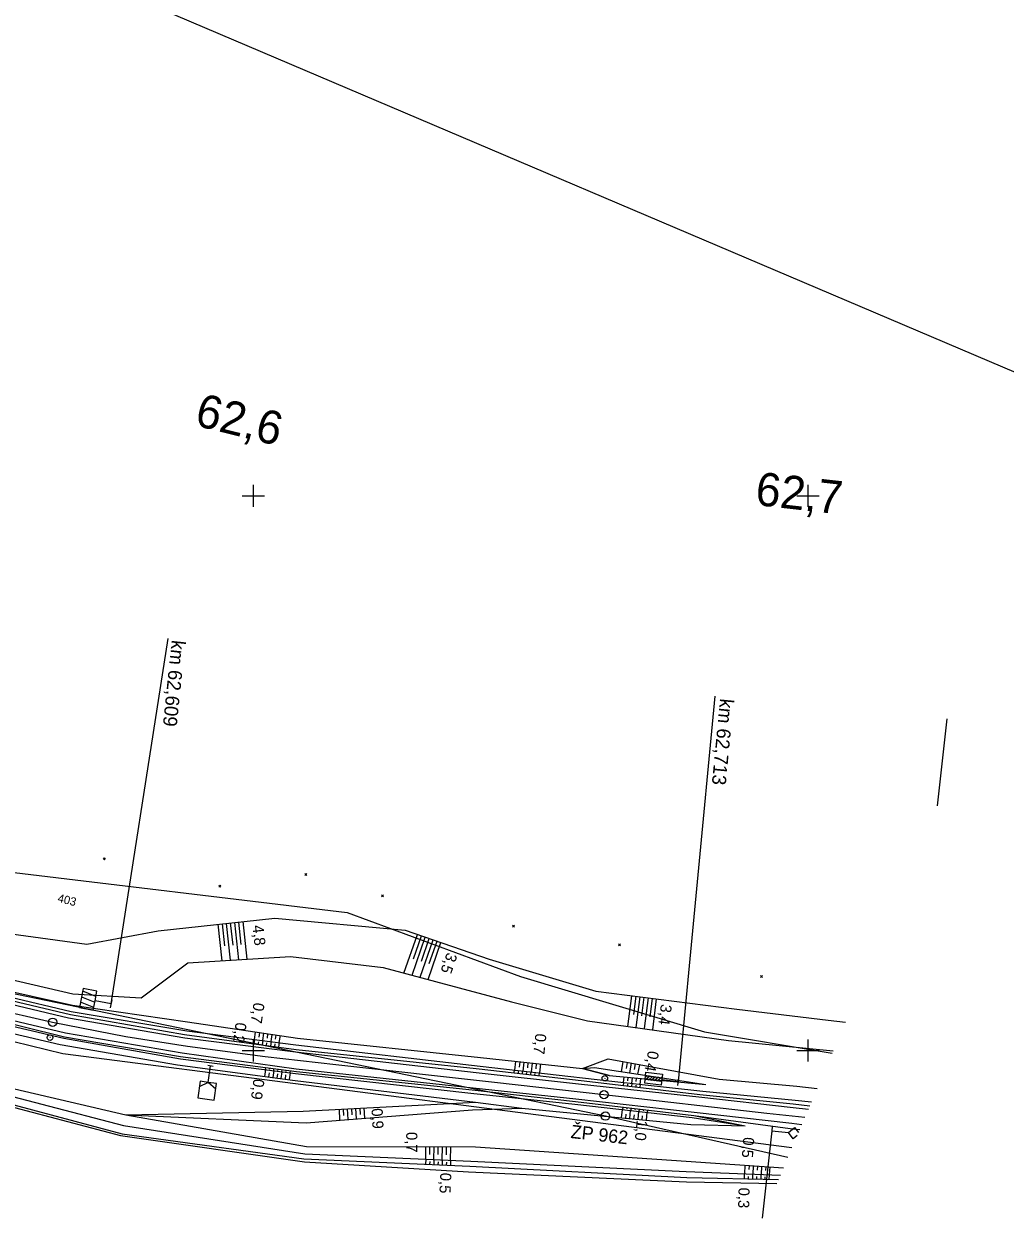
# Model space of a CAD drawing. Extents: x -805636 to -804553, y -1165340 to -1164656.
# Drawn here: x -804941.3 to -804764.5, y -1165130.2 to -1164914.9 of the extents above; entities that cross this region are included whole.
import ezdxf

# ---------------------------------------------------------------- set-up
doc = ezdxf.new("R2010")
doc.units = 0
for name, color, linetype in [('0381KM061-064P - Vrstva 1', 7, 'Continuous'), ('0381KM061-064P - Vrstva 4', 7, 'Continuous'), ('0381KM061-064P - Vrstva 48', 7, 'Continuous'), ('0381KM061-064P - Vrstva 49', 7, 'Continuous'), ('0381KM061-064P - Vrstva 51', 7, 'Continuous'), ('0381KM061-064P - Vrstva 57', 7, 'Continuous'), ('0381KM061-064P - Vrstva 7', 7, 'Continuous'), ('0381KM061-064P - Vrstva 8', 7, 'Continuous'), ('formát', 7, 'Continuous'), ('hran DP - hran DP', 7, 'Continuous'), ('krizky_1000 - Vrstva 1', 7, 'Continuous'), ('vyt_sit - polygon', 7, 'Continuous'), ('vyt_sit - stávající', 7, 'Continuous')]:
    doc.layers.add(name, color=color, linetype=linetype)

msp = doc.modelspace()

# ---------------------------------------------------------------- linework, layer by layer
at = {"layer": '0381KM061-064P - Vrstva 1'}
for points in [[(-805053.13, -1165050.53), (-805043.64, -1165055.76), (-805030.64, -1165062.45), (-805014.61, -1165069.88), (-804997.39, -1165076.92), (-804978.26, -1165083.66), (-804962.13, -1165088.54), (-804947.73, -1165092.28), (-804936.17, -1165094.91), (-804922.95, -1165097.46), (-804911.85, -1165099.22)], [(-804911.85, -1165099.22), (-804897.85, -1165101.07), (-804885.13, -1165102.52)], [(-804885.13, -1165102.52), (-804856.51, -1165105.73), (-804836.78, -1165107.96), (-804807.43, -1165111.28), (-804800.55, -1165112.05)]]:
    msp.add_lwpolyline(points, dxfattribs=at)
at = {"layer": '0381KM061-064P - Vrstva 4'}
for points in [[(-805080.47, -1165032.5), (-805059.19, -1165045.48), (-805045.86, -1165053.03), (-805029.76, -1165061.31), (-805010.76, -1165070.1), (-804990.66, -1165078.03), (-804974.85, -1165083.28), (-804955.57, -1165088.82), (-804933.31, -1165094.09), (-804912.36, -1165097.73), (-804892.37, -1165100.24)], [(-805080.11, -1165031.8), (-805059.18, -1165044.72), (-805045.31, -1165052.51), (-805029.54, -1165060.96), (-805010.72, -1165069.47), (-804990.45, -1165077.48), (-804974.57, -1165082.73), (-804955.28, -1165088.2), (-804932.96, -1165093.51), (-804912.39, -1165097.1), (-804892.28, -1165099.85)], [(-805082.03, -1165034.98), (-805060.37, -1165047.85), (-805047.54, -1165055.28), (-805031.06, -1165063.92), (-805012.89, -1165072.24), (-804991.69, -1165080.62), (-804976.05, -1165085.82), (-804956.42, -1165091.49), (-804933.87, -1165096.82), (-804912.82, -1165100.43), (-804892.24, -1165103.28)], [(-805082.08, -1165035.58), (-805060.58, -1165048.58), (-805047.98, -1165055.77), (-805031.23, -1165064.28), (-805013.07, -1165072.73), (-804991.62, -1165081.24), (-804976.47, -1165086.37), (-804956.64, -1165091.96), (-804934.05, -1165097.54), (-804913.13, -1165101.06), (-804892.22, -1165103.81)], [(-804892.37, -1165100.24), (-804859.84, -1165103.98), (-804840.8, -1165106.06), (-804819.65, -1165108.38), (-804802.7, -1165110.3), (-804799.92, -1165110.56)], [(-804892.28, -1165099.85), (-804859.81, -1165103.25), (-804840.34, -1165105.46), (-804819.52, -1165107.92), (-804802.69, -1165109.64), (-804799.68, -1165110)], [(-804892.24, -1165103.28), (-804860.33, -1165106.74), (-804841.86, -1165108.69), (-804820.53, -1165111.13), (-804802.92, -1165113.13), (-804801.1, -1165113.34)], [(-804892.22, -1165103.81), (-804860.51, -1165107.09), (-804841.9, -1165109.22), (-804820.58, -1165111.74), (-804803.21, -1165114.08), (-804801.49, -1165114.25)]]:
    msp.add_lwpolyline(points, dxfattribs=at)
at = {"layer": '0381KM061-064P - Vrstva 48'}
for p, q in [((-804905.61, -1165083.83), (-804906.31, -1165077.25)), ((-804905.14, -1165081.14), (-804905.57, -1165077.17)), ((-804904.11, -1165083.73), (-804904.83, -1165077.09)), ((-804903.65, -1165081.01), (-804904.08, -1165077.01)), ((-804902.62, -1165083.64), (-804903.34, -1165076.93)), ((-804902.16, -1165080.89), (-804902.59, -1165076.85)), ((-804901.12, -1165083.54), (-804901.85, -1165076.77)), ((-804872.83, -1165086.04), (-804870.41, -1165079.07)), ((-804871.37, -1165086.42), (-804868.99, -1165079.56)), ((-804871.14, -1165083.47), (-804869.7, -1165079.32)), ((-804869.92, -1165086.81), (-804867.58, -1165080.06)), ((-804869.7, -1165083.89), (-804868.29, -1165079.81)), ((-804868.47, -1165087.2), (-804866.16, -1165080.55)), ((-804868.26, -1165084.32), (-804866.87, -1165080.3)), ((-804832.45, -1165095.65), (-804831.74, -1165090.13)), ((-804831.42, -1165093.54), (-804831, -1165090.23)), ((-804830.97, -1165095.86), (-804830.25, -1165090.32)), ((-804829.94, -1165093.74), (-804829.51, -1165090.42)), ((-804829.48, -1165096.06), (-804828.77, -1165090.52)), ((-804828.45, -1165093.95), (-804828.02, -1165090.61)), ((-804827.99, -1165096.27), (-804827.28, -1165090.71)), ((-804899.77, -1165098.02), (-804899.57, -1165096.67)), ((-804898.95, -1165097.58), (-804898.83, -1165096.78)), ((-804898.29, -1165098.2), (-804898.09, -1165096.89)), ((-804897.46, -1165097.78), (-804897.35, -1165097)), ((-804896.8, -1165098.39), (-804896.61, -1165097.11)), ((-804895.98, -1165097.98), (-804895.87, -1165097.22)), ((-804895.31, -1165098.58), (-804895.12, -1165097.33)), ((-804899.78, -1165098.02), (-804899.89, -1165098.81)), ((-804899.08, -1165098.43), (-804899.15, -1165098.91)), ((-804898.29, -1165098.2), (-804898.4, -1165099.01)), ((-804897.59, -1165098.62), (-804897.66, -1165099.12)), ((-804896.8, -1165098.39), (-804896.92, -1165099.22)), ((-804896.11, -1165098.82), (-804896.17, -1165099.32)), ((-804895.32, -1165098.58), (-804895.43, -1165099.42)), ((-804897.81, -1165103.45), (-804897.97, -1165104.67)), ((-804897.8, -1165103.45), (-804897.75, -1165103.08)), ((-804897.04, -1165103.4), (-804897.01, -1165103.18)), ((-804896.32, -1165103.64), (-804896.49, -1165104.86)), ((-804896.31, -1165103.64), (-804896.27, -1165103.28)), ((-804895.55, -1165103.59), (-804895.52, -1165103.38)), ((-804894.83, -1165103.83), (-804895, -1165105.06)), ((-804894.83, -1165103.83), (-804894.78, -1165103.48)), ((-804894.06, -1165103.78), (-804894.04, -1165103.57)), ((-804893.34, -1165104.02), (-804893.29, -1165103.67)), ((-804852.96, -1165103.52), (-804853.02, -1165104.02)), ((-804852.82, -1165103.53), (-804852.66, -1165101.96)), ((-804852.24, -1165103.8), (-804852.27, -1165104.11)), ((-804852.01, -1165102.99), (-804851.91, -1165102.04)), ((-804851.47, -1165103.69), (-804851.53, -1165104.19)), ((-804851.33, -1165103.71), (-804851.17, -1165102.11)), ((-804850.52, -1165103.15), (-804850.42, -1165102.19)), ((-804849.98, -1165103.86), (-804850.04, -1165104.36)), ((-804849.84, -1165103.88), (-804849.67, -1165102.27)), ((-804849.03, -1165103.32), (-804848.93, -1165102.35)), ((-804848.35, -1165104.05), (-804848.18, -1165102.43)), ((-804833.61, -1165103.81), (-804833.29, -1165102.02)), ((-804832.74, -1165103.22), (-804832.55, -1165102.15)), ((-804832.13, -1165104.04), (-804831.81, -1165102.29)), ((-804831.26, -1165103.46), (-804831.07, -1165102.42)), ((-804830.65, -1165104.27), (-804830.33, -1165102.56)), ((-804897.13, -1165104.03), (-804897.23, -1165104.77)), ((-804895.64, -1165104.23), (-804895.74, -1165104.97)), ((-804894.16, -1165104.42), (-804894.26, -1165105.16)), ((-804893.35, -1165104.02), (-804893.51, -1165105.26)), ((-804850.75, -1165103.98), (-804850.78, -1165104.28)), ((-804849.26, -1165104.15), (-804849.29, -1165104.44)), ((-804848.49, -1165104.04), (-804848.55, -1165104.53)), ((-804833.23, -1165105.8), (-804833.29, -1165106.29)), ((-804833.24, -1165105.79), (-804833.15, -1165104.77)), ((-804832.46, -1165105.46), (-804832.4, -1165104.84)), ((-804831.74, -1165105.96), (-804831.8, -1165106.47)), ((-804831.75, -1165105.96), (-804831.66, -1165104.91)), ((-804830.97, -1165105.61), (-804830.91, -1165104.98)), ((-804830.26, -1165106.12), (-804830.16, -1165105.05)), ((-804832.51, -1165106.08), (-804832.54, -1165106.38)), ((-804831.02, -1165106.25), (-804831.05, -1165106.55)), ((-804830.25, -1165106.12), (-804830.31, -1165106.64)), ((-804833.4, -1165110.23), (-804833.45, -1165110.65)), ((-804832.66, -1165110.31), (-804832.68, -1165110.53)), ((-804884.38, -1165112.57), (-804884.48, -1165110.6)), ((-804883.67, -1165111.73), (-804883.73, -1165110.56)), ((-804882.88, -1165112.45), (-804882.99, -1165110.52)), ((-804882.18, -1165111.63), (-804882.24, -1165110.48)), ((-804881.39, -1165112.33), (-804881.49, -1165110.44)), ((-804880.68, -1165111.53), (-804880.74, -1165110.4)), ((-804879.89, -1165112.22), (-804879.99, -1165110.36)), ((-804833.61, -1165112.12), (-804833.46, -1165110.65)), ((-804832.86, -1165112.2), (-804832.79, -1165111.47)), ((-804832.11, -1165112.27), (-804831.97, -1165110.82)), ((-804831.91, -1165110.4), (-804831.96, -1165110.82)), ((-804831.37, -1165112.34), (-804831.3, -1165111.62)), ((-804831.17, -1165110.49), (-804831.19, -1165110.7)), ((-804830.62, -1165112.41), (-804830.48, -1165111)), ((-804830.42, -1165110.58), (-804830.47, -1165111)), ((-804829.87, -1165112.48), (-804829.81, -1165111.78)), ((-804829.68, -1165110.67), (-804829.7, -1165110.87)), ((-804829.13, -1165112.56), (-804828.99, -1165111.17)), ((-804828.93, -1165110.75), (-804828.98, -1165111.17)), ((-804868.92, -1165119.6), (-804868.91, -1165117.37)), ((-804868.17, -1165118.73), (-804868.16, -1165117.37)), ((-804867.42, -1165119.67), (-804867.41, -1165117.37)), ((-804866.67, -1165118.77), (-804866.66, -1165117.38)), ((-804865.92, -1165119.74), (-804865.91, -1165117.38)), ((-804865.17, -1165118.81), (-804865.16, -1165117.38)), ((-804864.42, -1165119.8), (-804864.41, -1165117.38)), ((-804868.92, -1165119.6), (-804868.96, -1165120.51)), ((-804868.18, -1165120), (-804868.21, -1165120.54)), ((-804867.42, -1165119.67), (-804867.46, -1165120.58)), ((-804866.68, -1165120.06), (-804866.71, -1165120.61)), ((-804865.92, -1165119.74), (-804865.96, -1165120.65)), ((-804865.19, -1165120.13), (-804865.21, -1165120.68)), ((-804864.42, -1165119.8), (-804864.46, -1165120.71)), ((-804811.36, -1165120.67), (-804811.46, -1165122.21)), ((-804810.61, -1165120.72), (-804810.66, -1165121.48)), ((-804809.86, -1165120.78), (-804809.96, -1165122.27)), ((-804809.11, -1165120.83), (-804809.16, -1165121.56)), ((-804808.36, -1165120.88), (-804808.46, -1165122.33)), ((-804807.62, -1165120.93), (-804807.67, -1165121.65)), ((-804806.87, -1165120.98), (-804806.97, -1165122.39)), ((-804811.47, -1165123.14), (-804811.45, -1165122.21)), ((-804810.72, -1165123.15), (-804810.71, -1165122.7)), ((-804809.97, -1165123.17), (-804809.95, -1165122.27)), ((-804809.22, -1165123.19), (-804809.21, -1165122.74)), ((-804808.47, -1165123.2), (-804808.45, -1165122.33)), ((-804807.72, -1165123.22), (-804807.71, -1165122.79)), ((-804806.97, -1165123.24), (-804806.95, -1165122.39))]:
    msp.add_line(p, q, dxfattribs=at)
at = {"layer": '0381KM061-064P - Vrstva 49'}
for p, q in [((-804926.67, -1165065.65), (-804927.02, -1165065.3)), ((-804926.67, -1165065.3), (-804927.02, -1165065.65)), ((-804890.35, -1165068.45), (-804890.7, -1165068.09)), ((-804890.35, -1165068.09), (-804890.7, -1165068.45)), ((-804905.87, -1165070.56), (-804906.22, -1165070.21)), ((-804905.87, -1165070.21), (-804906.22, -1165070.56)), ((-804876.55, -1165072.32), (-804876.9, -1165071.96)), ((-804876.55, -1165071.96), (-804876.9, -1165072.32)), ((-804852.89, -1165077.76), (-804853.25, -1165077.4)), ((-804852.89, -1165077.4), (-804853.25, -1165077.76)), ((-804833.78, -1165081.15), (-804834.13, -1165080.8)), ((-804833.78, -1165080.8), (-804834.13, -1165081.15)), ((-804808.18, -1165086.83), (-804808.54, -1165086.48)), ((-804808.18, -1165086.48), (-804808.54, -1165086.83))]:
    msp.add_line(p, q, dxfattribs=at)
for points in [[(-805084.74, -1165039.06), (-805061.55, -1165052.74), (-805034.17, -1165068.7), (-805016.31, -1165078.58), (-804984.31, -1165094.26), (-804952.92, -1165105.84), (-804923.4, -1165113.55), (-804890.69, -1165118.62), (-804860.79, -1165119.97), (-804821.99, -1165121.8), (-804804.98, -1165122.47)], [(-805085.43, -1165039.91), (-805061.8, -1165053.37), (-805034.45, -1165069.27), (-805016.82, -1165079.3), (-804984.87, -1165094.97), (-804952.63, -1165107.29), (-804923.66, -1165115.02), (-804890.91, -1165119.51), (-804860.93, -1165120.87), (-804821.85, -1165122.9), (-804805.33, -1165123.27)], [(-805060.73, -1165049.17), (-805031.5, -1165064.84), (-805013.36, -1165073.14), (-804991.7, -1165081.91), (-804976.67, -1165086.76), (-804957.06, -1165092.46), (-804934.14, -1165097.81), (-804913.12, -1165101.52), (-804892.37, -1165104.14)], [(-805060.73, -1165049.17), (-805047.98, -1165055.77), (-805031.23, -1165064.28), (-805013.07, -1165072.73), (-804991.62, -1165081.24), (-804976.47, -1165086.37), (-804956.64, -1165091.96), (-804934.05, -1165097.54), (-804913.13, -1165101.06), (-804892.22, -1165103.81), (-804860.51, -1165107.09), (-804841.9, -1165109.22), (-804820.58, -1165111.74), (-804811.31, -1165113.56)], [(-805014.74, -1165060.42), (-805013.72, -1165061.35), (-805008.65, -1165063.79), (-805007.41, -1165061.32), (-805005.07, -1165061.94), (-804999.18, -1165065.52), (-804973.34, -1165074.67), (-804953.36, -1165077.67), (-804930.03, -1165080.86)], [(-805033.41, -1165066.35), (-805014.98, -1165076.25), (-804982.53, -1165092.31), (-804953.12, -1165104.6), (-804922.96, -1165111.59), (-804890.43, -1165117.32), (-804859.92, -1165117.39), (-804821.94, -1165119.94), (-804804.42, -1165121.15)], [(-805032.39, -1165065.25), (-805013.72, -1165073.73), (-804991.69, -1165082.79), (-804976.92, -1165087.4), (-804957.71, -1165093.59), (-804934.8, -1165098.93), (-804913.68, -1165102.56), (-804892.44, -1165105.41)], [(-805010.72, -1165069.47), (-804990.45, -1165077.48), (-804974.57, -1165082.73), (-804955.28, -1165088.2), (-804932.96, -1165093.51), (-804912.39, -1165097.1), (-804892.28, -1165099.85), (-804859.81, -1165103.25), (-804840.34, -1165105.46), (-804819.52, -1165107.92), (-804802.69, -1165109.64), (-804799.68, -1165110)], [(-804995.17, -1165073.22), (-804973.67, -1165080.7), (-804954.98, -1165086.86), (-804932.57, -1165091.85), (-804911.87, -1165094.85)], [(-804994.86, -1165072.51), (-804973.16, -1165079.86), (-804954.29, -1165084.75), (-804932.5, -1165089.79), (-804920.22, -1165090.5), (-804911.77, -1165084.22), (-804893.29, -1165083.05), (-804876.57, -1165085.04), (-804853.44, -1165091.21), (-804839.72, -1165094.63), (-804814.35, -1165098.18)], [(-804930.03, -1165080.86), (-804917.17, -1165078.41), (-804896.14, -1165076.16), (-804872.64, -1165078.3), (-804857.5, -1165083.55), (-804838.27, -1165089.29), (-804812.85, -1165092.56), (-804796.39, -1165094.52), (-804793.24, -1165094.87)], [(-804955.12, -1165087.69), (-804932.8, -1165092.95), (-804911.98, -1165096.48), (-804892.31, -1165098.96)], [(-804911.87, -1165094.85), (-804892.03, -1165097.79)], [(-804892.31, -1165098.96), (-804859.08, -1165102.8), (-804835.93, -1165105.5), (-804818.93, -1165107.36), (-804802.32, -1165108.93), (-804799.37, -1165109.27)], [(-804892.03, -1165097.79), (-804859.05, -1165101.29), (-804840.64, -1165103.22)], [(-804814.35, -1165098.18), (-804795.44, -1165100.05)], [(-804840.64, -1165103.22), (-804836.05, -1165101.51), (-804816.03, -1165105.18), (-804802.02, -1165106.41), (-804798.34, -1165106.84)], [(-804840.64, -1165103.22), (-804838.47, -1165103.07), (-804818.4, -1165106.14)], [(-804840.64, -1165103.22), (-804835.82, -1165104.53), (-804840.64, -1165103.22), (-804835.82, -1165104.53), (-804818.4, -1165106.14)], [(-804892.44, -1165105.41), (-804859.96, -1165109.29), (-804851.61, -1165110.39), (-804821.13, -1165113.33), (-804811.31, -1165113.56)], [(-804892.37, -1165104.14), (-804860.79, -1165107.69), (-804842.05, -1165109.66), (-804820.85, -1165112.11), (-804811.31, -1165113.56)], [(-804922.96, -1165111.59), (-804890.98, -1165110.95), (-804859.96, -1165109.29)], [(-804922.96, -1165111.59), (-804890.49, -1165113.04), (-804860.47, -1165110.71), (-804851.61, -1165110.39)]]:
    msp.add_lwpolyline(points, dxfattribs=at)
at = {"layer": '0381KM061-064P - Vrstva 51'}
msp.add_lwpolyline([(-805085.93, -1165040.55), (-805062.08, -1165054.12), (-805034.69, -1165069.73), (-805017.21, -1165079.65), (-804985.71, -1165095.39), (-804952.66, -1165107.75), (-804923.93, -1165115.31), (-804890.75, -1165120.1), (-804861.18, -1165121.85), (-804821.92, -1165123.67), (-804805.64, -1165124)], dxfattribs=at)
at = {"layer": '0381KM061-064P - Vrstva 7'}
for p, q in [((-804925.59, -1165091.6), (-804915.32, -1165025.75)), ((-804930.94, -1165090.31), (-804928.58, -1165091.28)), ((-804928.39, -1165090.29), (-804930.75, -1165089.33)), ((-804925.73, -1165092.34), (-804925.45, -1165090.86)), ((-804928.77, -1165092.26), (-804931.13, -1165091.29)), ((-804936.58, -1165097.69), (-804936.68, -1165097.67)), ((-804907.2, -1165102.86), (-804908.19, -1165102.73)), ((-804908.11, -1165105.77), (-804907.69, -1165102.79)), ((-804836.67, -1165105.01), (-804836.57, -1165105.03))]:
    msp.add_line(p, q, dxfattribs=at)
for points in [[(-804925.59, -1165091.6), (-804928.53, -1165091.03), (-804928.2, -1165089.31), (-804930.66, -1165088.84), (-804931.32, -1165092.27), (-804928.86, -1165092.75), (-804928.53, -1165091.03)], [(-804908.11, -1165105.77), (-804909.59, -1165105.56), (-804910, -1165108.53), (-804907.03, -1165108.94), (-804906.62, -1165105.97), (-804908.11, -1165105.77)], [(-804906.76, -1165106.96), (-804908.11, -1165105.77), (-804909.73, -1165106.55)]]:
    msp.add_lwpolyline(points, dxfattribs=at)
for centre, radius in [((-804936.17, -1165094.91), 0.75), ((-804936.63, -1165097.68), 0.5), ((-804836.62, -1165105.02), 0.5), ((-804836.78, -1165107.96), 0.75)]:
    msp.add_circle(centre, radius, dxfattribs=at)
at = {"layer": '0381KM061-064P - Vrstva 8'}
for p, q in [((-804823.36, -1165105.59), (-804816.74, -1165036.14)), ((-804776.65, -1165055.87), (-804774.89, -1165040.2)), ((-804829.06, -1165104.6), (-804829.31, -1165104.79)), ((-804828.53, -1165104.66), (-804829.3, -1165105.27)), ((-804828.01, -1165104.72), (-804828.78, -1165105.33)), ((-804827.48, -1165104.77), (-804828.25, -1165105.39)), ((-804826.95, -1165104.83), (-804827.72, -1165105.45)), ((-804826.42, -1165104.89), (-804827.2, -1165105.51)), ((-804826.35, -1165105.31), (-804826.67, -1165105.57)), ((-804823.44, -1165106.34), (-804823.28, -1165104.85)), ((-804806.51, -1165114.46), (-804808.28, -1165130.22)), ((-804806.43, -1165113.71), (-804806.59, -1165115.21))]:
    msp.add_line(p, q, dxfattribs=at)
for points in [[(-804826.45, -1165106.25), (-804829.43, -1165105.91), (-804829.21, -1165103.92), (-804826.23, -1165104.26), (-804826.45, -1165106.25)], [(-804826.34, -1165105.26), (-804823.36, -1165105.59)], [(-804806.51, -1165114.46), (-804803.53, -1165114.8), (-804802.42, -1165113.91), (-804801.72, -1165114.8)], [(-804801.95, -1165115.35), (-804802.65, -1165115.9), (-804803.53, -1165114.8)]]:
    msp.add_lwpolyline(points, dxfattribs=at)
msp.add_lwpolyline([(-804826.38, -1165105.6), (-804829.36, -1165105.26), (-804829.28, -1165104.57), (-804826.3, -1165104.91)], close=True, dxfattribs=at)
at = {"layer": 'formát'}
msp.add_line((-804746.36, -1164984.69), (-804939.6, -1164902.47), dxfattribs=at)
at = {"layer": 'hran DP - hran DP'}
for p, q in [((-804991.93, -1165061.99), (-804883.1, -1165075.15)), ((-804883.1, -1165075.15), (-804851.84, -1165086.69)), ((-804851.84, -1165086.69), (-804818.68, -1165096.66)), ((-804934.32, -1165100.62), (-804968.55, -1165092.26)), ((-804818.68, -1165096.66), (-804795.63, -1165100.48)), ((-804802.89, -1165117.55), (-804934.32, -1165100.62))]:
    msp.add_line(p, q, dxfattribs=at)
at = {"layer": 'krizky_1000 - Vrstva 1'}
for points in [[(-804900, -1164998), (-804900, -1165002)], [(-804800, -1164998), (-804800, -1165002)], [(-804902, -1165000), (-804898, -1165000)], [(-804802, -1165000), (-804798, -1165000)], [(-804900, -1165098), (-804900, -1165102)], [(-804800, -1165098), (-804800, -1165102)], [(-804902, -1165100), (-804898, -1165100)], [(-804802, -1165100), (-804798, -1165100)]]:
    msp.add_lwpolyline(points, dxfattribs=at)
at = {"layer": 'vyt_sit - polygon'}
for p, q in [((-804836.52, -1165111.83), (-805011.29, -1165075.75)), ((-804803.63, -1165119.28), (-804836.52, -1165111.83))]:
    msp.add_line(p, q, dxfattribs=at)
at = {"layer": 'vyt_sit - stávající'}
msp.add_line((-804836.57, -1165111.8), (-804836.48, -1165111.85), dxfattribs=at)
msp.add_circle((-804836.52, -1165111.83), 0.756, dxfattribs=at)

# ---------------------------------------------------------------- texts
at = {"layer": '0381KM061-064P - Vrstva 48'}
for s, rotation, p in [('4,8', 276.1274, (-804900.15, -1165077.5)), ('3,5', 250.8741, (-804865.05, -1165082.21)), ('0,7', 261.5641, (-804899.92, -1165091.28)), ('3,4', 262.6656, (-804826.51, -1165091.58)), ('0,2', 262.2041, (-804903.16, -1165094.86)), ('0,7', 264.0185, (-804849.13, -1165096.87)), ('0,4', 259.6289, (-804828.81, -1165099.95)), ('0,9', 262.3554, (-804899.94, -1165105.03)), ('0,9', 273.0779, (-804878.69, -1165110.47)), ('1,0', 264.4873, (-804830.87, -1165112.47)), ('0,7', 269.8704, (-804872.42, -1165114.69)), ('0,5', 266.024, (-804811.67, -1165115.58)), ('0,5', 267.3952, (-804866.27, -1165122.01)), ('0,3', 268.6994, (-804812.52, -1165124.7))]:
    msp.add_text(s, height=2, rotation=rotation, dxfattribs=at).set_placement(p)
at = {"layer": '0381KM061-064P - Vrstva 57'}
msp.add_text('403', height=1.5, rotation=345.9546, dxfattribs=at).set_placement((-804935.37, -1165073.19))
at = {"layer": '0381KM061-064P - Vrstva 7'}
for s, height, rotation, p in [('62,6', 6, 346.0635, (-804910.76, -1164987.27)), ('62,7', 6, 353.5516, (-804809.66, -1165001.63)), ('km 62,609', 2.5, 264.0663, (-804914.69, -1165025.94))]:
    msp.add_text(s, height=height, rotation=rotation, dxfattribs=at).set_placement(p)
at = {"layer": '0381KM061-064P - Vrstva 8'}
msp.add_text('km 62,713', height=2.5, rotation=264.5581, dxfattribs=at).set_placement((-804815.85, -1165036.49))
at = {"layer": 'vyt_sit - stávající'}
msp.add_text('ŽP 962', height=2.4, rotation=353.5611, dxfattribs=at).set_placement((-804842.86, -1165115.77))

doc.saveas('drawing.dxf')
